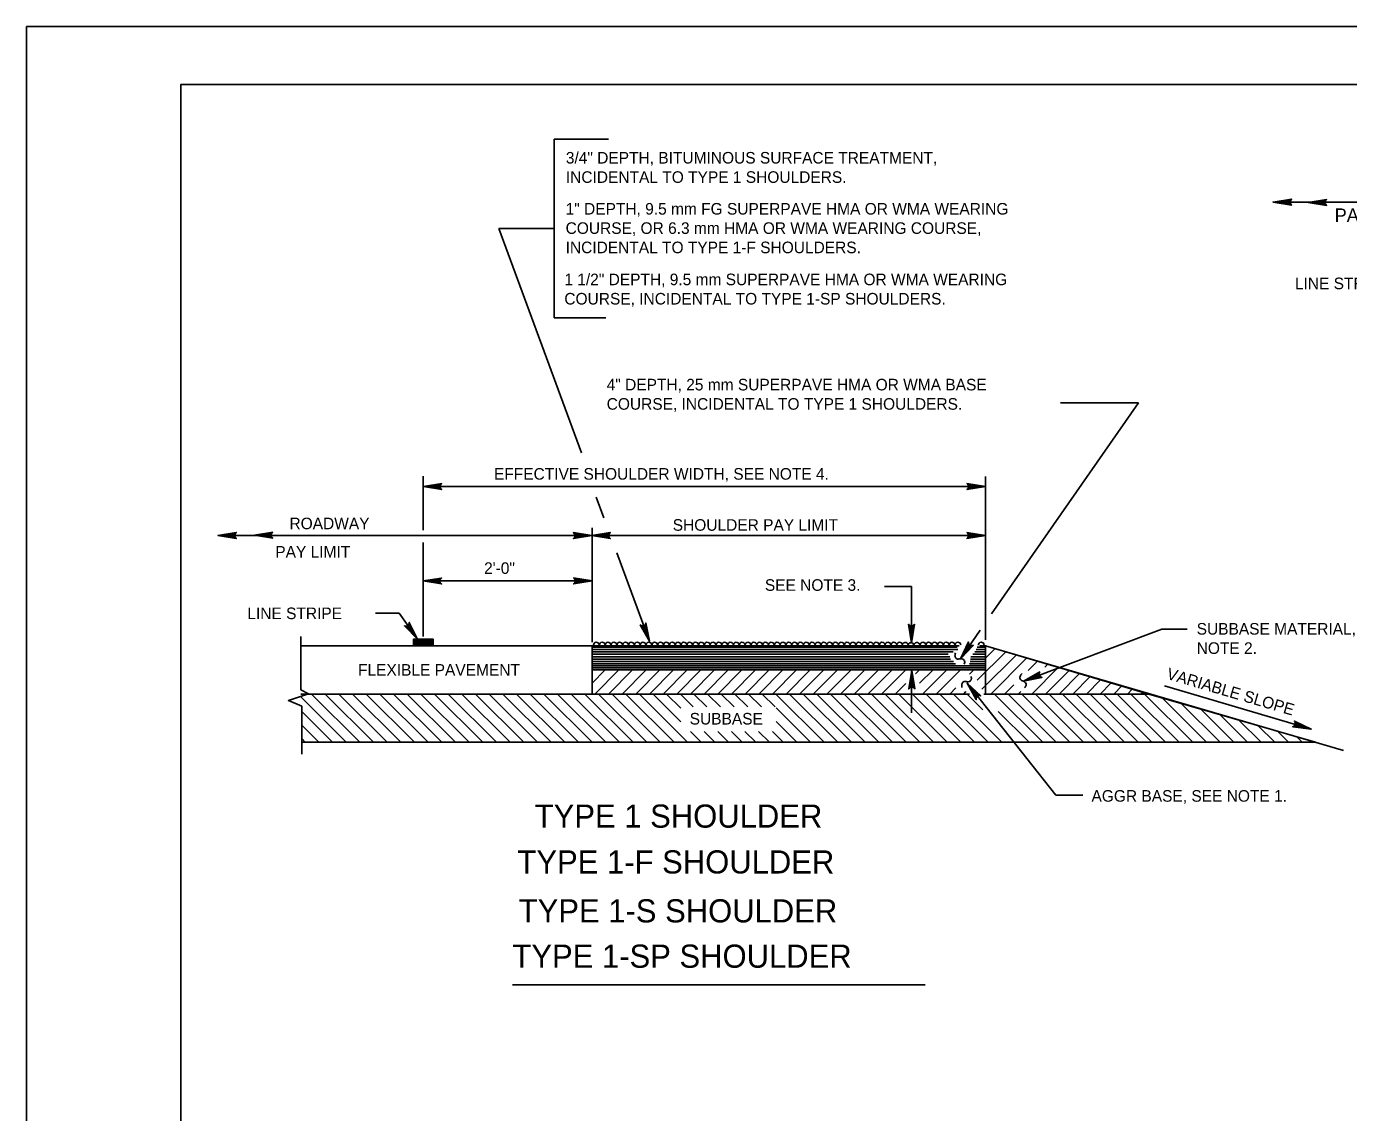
# Model space of a CAD drawing. Extents: x 638216 to 639962, y 297510 to 299292.
# Drawn here: x 638215.9 to 638558.2, y 299010.9 to 299292.2 of the extents above; entities that cross this region are included whole.
import ezdxf

# ---------------------------------------------------------------- set-up
doc = ezdxf.new("R2010")
doc.units = 0
for name, color, linetype in [('1', 7, 'Continuous'), ('2', 7, 'Continuous'), ('3', 7, 'Continuous'), ('PLT-BNDY', 7, 'Continuous')]:
    doc.layers.add(name, color=color, linetype=linetype)

msp = doc.modelspace()

# ---------------------------------------------------------------- linework, layer by layer
at = {"layer": '1'}
msp.add_lwpolyline([(639041.88, 298713.24), (639041.88, 299277.24), (638255.88, 299277.24), (638255.88, 298713.24), (639041.88, 298713.24), (639041.88, 298739.6), (638841.88, 298739.6), (638841.88, 298804.28), (639041.88, 298804.28), (639041.88, 298833.24), (638841.88, 298833.24), (638841.88, 298713.24), (638920.69, 298713.24), (638920.69, 298739.6), (638920.69, 298713.24), (638997.69, 298713.24), (638997.69, 298739.6), (638997.69, 298727.28), (639041.88, 298727.28)], dxfattribs=at)
at = {"layer": '2'}
for p, q in [((638352.54, 299216.78), (638352.54, 299263.08)), ((638366.62, 299263.08), (638352.54, 299263.08)), ((638540.27, 299246.73), (638634.27, 299246.73)), ((638352.54, 299239.93), (638338.17, 299239.93)), ((638359.61, 299181.77), (638338.17, 299239.93)), ((638365.93, 299216.78), (638352.54, 299216.78)), ((638503.83, 299194.7), (638465.79, 299140.08)), ((638483.63, 299194.7), (638503.83, 299194.7)), ((638318.61, 299161.77), (638318.61, 299175.77)), ((638464.2, 299133.35), (638464.2, 299175.7)), ((638318.65, 299173.05), (638464.18, 299173.05)), ((638365.39, 299164.96), (638363.42, 299170.3)), ((638266.88, 299160.36), (638362.28, 299160.36)), ((638362.28, 299160.36), (638464.18, 299160.36)), ((638362.38, 299132.79), (638362.38, 299162.4)), ((638318.61, 299134.22), (638318.61, 299158.59)), ((638376.92, 299133.66), (638368.73, 299155.9)), ((638318.59, 299148.61), (638362.34, 299148.61)), ((638438.08, 299147.18), (638445.02, 299147.18)), ((638445.02, 299132.61), (638445.02, 299147.18)), ((638306.27, 299140.28), (638312.42, 299140.28)), ((638312.42, 299140.28), (638317.03, 299133.74)), ((638286.96, 299120.41), (638286.96, 299134.22)), ((638462.82, 299135.82), (638457.7, 299128.45)), ((638509.87, 299136.15), (638474.05, 299122.67)), ((638509.87, 299136.15), (638516.42, 299136.15)), ((638287.15, 299131.82), (638457.41, 299131.82)), ((638362.34, 299119.32), (638362.34, 299131.82)), ((638462.7, 299131.82), (638464.23, 299131.82)), ((638464.23, 299119.32), (638464.23, 299131.82)), ((638464.23, 299131.82), (638556.9, 299104.7)), ((638506.52, 299119.32), (638464.23, 299131.82)), ((638464.23, 299131.82), (638464.23, 299125.57)), ((638362.34, 299125.57), (638464.23, 299125.57)), ((638464.23, 299125.57), (638362.34, 299125.57)), ((638362.34, 299125.57), (638362.34, 299119.32)), ((638445.02, 299114.41), (638445.02, 299125.57)), ((638286.96, 299119.32), (638460.1, 299119.32)), ((638385.32, 299112.12), (638378.12, 299119.32)), ((638385.32, 299115.66), (638381.65, 299119.32)), ((638388.52, 299115.99), (638385.19, 299119.32)), ((638392.05, 299115.99), (638388.72, 299119.32)), ((638395.59, 299115.99), (638392.26, 299119.32)), ((638399.12, 299115.99), (638395.8, 299119.32)), ((638402.66, 299115.99), (638399.33, 299119.32)), ((638406.2, 299115.99), (638402.87, 299119.32)), ((638409.73, 299115.99), (638406.4, 299119.32)), ((638482.42, 299093.14), (638459.91, 299121.63)), ((638463.81, 299119.32), (638506.52, 299119.32)), ((638506.52, 299119.32), (638549.65, 299106.82)), ((638510.57, 299121.41), (638548.55, 299110.24)), ((638418.9, 299106.82), (638409.97, 299115.75)), ((638390.62, 299106.82), (638387.79, 299109.65)), ((638394.15, 299106.82), (638391.33, 299109.65)), ((638397.69, 299106.82), (638394.86, 299109.65)), ((638401.23, 299106.82), (638398.4, 299109.65)), ((638404.76, 299106.82), (638401.93, 299109.65)), ((638408.3, 299106.82), (638405.47, 299109.65)), ((638411.83, 299106.82), (638409.01, 299109.65)), ((638415.37, 299106.82), (638409.97, 299112.22)), ((638287.15, 299106.82), (638549.65, 299106.82)), ((638549.65, 299106.82), (638287.15, 299106.82)), ((638482.42, 299093.14), (638489.37, 299093.14)), ((638341.72, 299044.02), (638448.55, 299044.02))]:
    msp.add_line(p, q, dxfattribs=at)
for points in [[(638543.19, 299246.18), (638543.02, 299246.51), (638538.65, 299246.75), (638543.19, 299246.18), (638543.43, 299245.98), (638538.65, 299246.75), (638543.02, 299246.97), (638543.18, 299247.29), (638538.65, 299246.75), (638543.43, 299247.51), (638543.18, 299247.29)], [(638543.19, 299246.18), (638543.02, 299246.51), (638538.65, 299246.75), (638543.19, 299246.18), (638543.43, 299245.98), (638538.65, 299246.75), (638543.02, 299246.97), (638543.18, 299247.29), (638538.65, 299246.75), (638543.43, 299247.51), (638543.18, 299247.29)], [(638543.23, 299246.16), (638543.06, 299246.49), (638538.69, 299246.73), (638543.23, 299246.16), (638543.46, 299245.96), (638538.69, 299246.73), (638543.06, 299246.95), (638543.22, 299247.27), (638538.69, 299246.73), (638543.46, 299247.49), (638543.22, 299247.27)], [(638552.3, 299246.08), (638552.13, 299246.41), (638547.76, 299246.65), (638552.3, 299246.08), (638552.53, 299245.89), (638547.76, 299246.65), (638552.12, 299246.87), (638552.28, 299247.2), (638547.76, 299246.65), (638552.53, 299247.41), (638552.28, 299247.2)], [(638552.3, 299246.08), (638552.13, 299246.41), (638547.76, 299246.65), (638552.3, 299246.08), (638552.53, 299245.89), (638547.76, 299246.65), (638552.12, 299246.87), (638552.28, 299247.2), (638547.76, 299246.65), (638552.53, 299247.41), (638552.28, 299247.2)], [(638323.19, 299172.48), (638323.02, 299172.81), (638318.65, 299173.05), (638323.19, 299172.48), (638323.42, 299172.28), (638318.65, 299173.05), (638323.02, 299173.27), (638323.18, 299173.59), (638318.65, 299173.05), (638323.42, 299173.81), (638323.18, 299173.59)], [(638459.63, 299173.62), (638459.8, 299173.29), (638464.18, 299173.05), (638459.63, 299173.62), (638459.4, 299173.82), (638464.18, 299173.05), (638459.81, 299172.84), (638459.65, 299172.51), (638464.18, 299173.05), (638459.4, 299172.29), (638459.65, 299172.51)], [(638269.98, 299159.8), (638269.81, 299160.13), (638265.44, 299160.37), (638269.98, 299159.8), (638270.22, 299159.6), (638265.44, 299160.37), (638269.81, 299160.59), (638269.97, 299160.91), (638265.44, 299160.37), (638270.22, 299161.13), (638269.97, 299160.91)], [(638270.02, 299159.79), (638269.85, 299160.12), (638265.48, 299160.36), (638270.02, 299159.79), (638270.25, 299159.59), (638265.48, 299160.36), (638269.85, 299160.57), (638270.01, 299160.9), (638265.48, 299160.36), (638270.25, 299161.12), (638270.01, 299160.9)], [(638279.43, 299159.89), (638279.27, 299160.22), (638274.89, 299160.46), (638279.43, 299159.89), (638279.67, 299159.69), (638274.89, 299160.46), (638279.26, 299160.68), (638279.42, 299161), (638274.89, 299160.46), (638279.67, 299161.22), (638279.42, 299161)], [(638357.74, 299160.93), (638357.91, 299160.6), (638362.28, 299160.36), (638357.74, 299160.93), (638357.51, 299161.13), (638362.28, 299160.36), (638357.92, 299160.14), (638357.76, 299159.82), (638362.28, 299160.36), (638357.51, 299159.6), (638357.76, 299159.82)], [(638366.82, 299159.79), (638366.66, 299160.12), (638362.28, 299160.36), (638366.82, 299159.79), (638367.06, 299159.59), (638362.28, 299160.36), (638366.65, 299160.57), (638366.81, 299160.9), (638362.28, 299160.36), (638367.06, 299161.12), (638366.81, 299160.9)], [(638459.63, 299160.93), (638459.8, 299160.6), (638464.18, 299160.36), (638459.63, 299160.93), (638459.4, 299161.13), (638464.18, 299160.36), (638459.81, 299160.14), (638459.65, 299159.82), (638464.18, 299160.36), (638459.4, 299159.6), (638459.65, 299159.82)], [(638323.13, 299148.04), (638322.96, 299148.37), (638318.59, 299148.61), (638323.13, 299148.04), (638323.37, 299147.84), (638318.59, 299148.61), (638322.96, 299148.83), (638323.12, 299149.15), (638318.59, 299148.61), (638323.37, 299149.37), (638323.12, 299149.15)], [(638357.8, 299149.18), (638357.97, 299148.85), (638362.34, 299148.61), (638357.8, 299149.18), (638357.57, 299149.38), (638362.34, 299148.61), (638357.97, 299148.4), (638357.81, 299148.07), (638362.34, 299148.61), (638357.57, 299147.85), (638357.81, 299148.07)], [(638315, 299137.55), (638314.82, 299137.22), (638317.15, 299133.51), (638315, 299137.55), (638315.02, 299137.85), (638317.15, 299133.51), (638314.45, 299136.95), (638314.1, 299136.9), (638317.15, 299133.51), (638313.77, 299136.97), (638314.1, 299136.9)], [(638375.08, 299137.06), (638375.45, 299137.02), (638377.17, 299132.99), (638375.08, 299137.06), (638374.82, 299137.21), (638377.17, 299132.99), (638375.88, 299137.17), (638376.13, 299137.43), (638377.17, 299132.99), (638376.25, 299137.74), (638376.13, 299137.43)], [(638445.59, 299137.15), (638445.26, 299136.98), (638445.02, 299132.61), (638445.59, 299137.15), (638445.79, 299137.38), (638445.02, 299132.61), (638444.81, 299136.97), (638444.48, 299137.13), (638445.02, 299132.61), (638444.26, 299137.38), (638444.48, 299137.13)], [(638316.07, 299133.33), (638316.24, 299133.51)], [(638316.07, 299132.16), (638317.42, 299133.51)], [(638316.07, 299132.51), (638317.06, 299133.51)], [(638316.07, 299132.86), (638316.71, 299133.51)], [(638316.07, 299133.22), (638316.36, 299133.51)], [(638316.17, 299131.91), (638317.77, 299133.51)], [(638316.52, 299131.91), (638318.12, 299133.51)], [(638316.88, 299131.91), (638318.48, 299133.51)], [(638317.23, 299131.91), (638318.83, 299133.51)], [(638317.58, 299131.91), (638319.18, 299133.51)], [(638317.94, 299131.91), (638319.54, 299133.51)], [(638318.29, 299131.91), (638319.89, 299133.51)], [(638318.64, 299131.91), (638320.25, 299133.51)], [(638319, 299131.91), (638320.6, 299133.51)], [(638319.35, 299131.91), (638320.95, 299133.51)], [(638319.7, 299131.91), (638321.2, 299133.4)], [(638320.06, 299131.91), (638321.2, 299133.05)], [(638320.41, 299131.91), (638321.2, 299132.69)], [(638320.76, 299131.91), (638321.2, 299132.34)], [(638321, 299131.91), (638321.2, 299132.1)], [(638321.12, 299131.91), (638321.2, 299131.98)], [(638362.34, 299131.75), (638362.41, 299131.82)], [(638362.34, 299131.49), (638456.84, 299131.49)], [(638362.34, 299130.87), (638457.08, 299130.87)], [(638362.34, 299130.24), (638455.87, 299130.24)], [(638362.34, 299129.62), (638454.55, 299129.62)], [(638460.76, 299131.85), (638460.39, 299131.9), (638457.7, 299128.45), (638460.76, 299131.85), (638461.05, 299131.93), (638457.7, 299128.45), (638460.01, 299132.16), (638459.84, 299132.48), (638457.7, 299128.45), (638459.8, 299132.8), (638459.84, 299132.48)], [(638460.89, 299129.62), (638464.23, 299129.62)], [(638461.41, 299130.24), (638464.23, 299130.24)], [(638461.79, 299130.87), (638464.23, 299130.87)], [(638462.08, 299131.49), (638464.23, 299131.49)], [(638462.08, 299122.89), (638469.46, 299130.27)], [(638463.28, 299120.55), (638472.19, 299129.47)], [(638464.23, 299128.57), (638466.73, 299131.08)], [(638362.34, 299128.99), (638454.94, 299128.99)], [(638362.34, 299128.37), (638455.17, 299128.37)], [(638362.34, 299127.74), (638455.89, 299127.74)], [(638362.34, 299127.12), (638456.41, 299127.12)], [(638362.34, 299126.58), (638464.23, 299126.58)], [(638362.34, 299126.07), (638464.23, 299126.07)], [(638460.08, 299127.12), (638464.23, 299127.12)], [(638460.22, 299127.74), (638464.23, 299127.74)], [(638460.36, 299128.37), (638464.23, 299128.37)], [(638460.41, 299128.99), (638464.23, 299128.99)], [(638465.58, 299119.32), (638474.92, 299128.66)], [(638475.24, 299125.44), (638477.65, 299127.85)], [(638476.19, 299119.32), (638483.11, 299126.24)], [(638479.58, 299126.25), (638480.38, 299127.05)], [(638362.34, 299122.14), (638365.76, 299125.57)], [(638363.05, 299119.32), (638369.3, 299125.57)], [(638366.58, 299119.32), (638372.83, 299125.57)], [(638370.12, 299119.32), (638376.37, 299125.57)], [(638373.66, 299119.32), (638379.91, 299125.57)], [(638377.19, 299119.32), (638383.44, 299125.57)], [(638380.73, 299119.32), (638386.98, 299125.57)], [(638384.26, 299119.32), (638390.51, 299125.57)], [(638387.8, 299119.32), (638394.05, 299125.57)], [(638391.33, 299119.32), (638397.58, 299125.57)], [(638394.87, 299119.32), (638401.12, 299125.57)], [(638398.41, 299119.32), (638404.66, 299125.57)], [(638401.94, 299119.32), (638408.19, 299125.57)], [(638405.48, 299119.32), (638411.73, 299125.57)], [(638409.01, 299119.32), (638415.26, 299125.57)], [(638412.55, 299119.32), (638418.8, 299125.57)], [(638416.08, 299119.32), (638422.33, 299125.57)], [(638419.62, 299119.32), (638425.87, 299125.57)], [(638423.15, 299119.32), (638429.4, 299125.57)], [(638426.69, 299119.32), (638432.94, 299125.57)], [(638430.22, 299119.32), (638436.47, 299125.57)], [(638433.76, 299119.32), (638440.01, 299125.57)], [(638437.3, 299119.32), (638443.55, 299125.57)], [(638444.55, 299120.9), (638444.87, 299121.07), (638445.11, 299125.44), (638444.55, 299120.9), (638444.35, 299120.66), (638445.11, 299125.44), (638445.33, 299121.07), (638445.66, 299120.91), (638445.11, 299125.44), (638445.87, 299120.66), (638445.66, 299120.91)], [(638446.05, 299124.54), (638447.08, 299125.57)], [(638447.15, 299122.1), (638450.62, 299125.57)], [(638447.9, 299119.32), (638454.15, 299125.57)], [(638451.44, 299119.32), (638457.69, 299125.57)], [(638460.07, 299124.42), (638461.22, 299125.57)], [(638478.5, 299123.73), (638478.23, 299123.98), (638474.05, 299122.67), (638478.5, 299123.73), (638478.79, 299123.63), (638474.05, 299122.67), (638478.06, 299124.41), (638478.1, 299124.77), (638474.05, 299122.67), (638478.25, 299125.06), (638478.1, 299124.77)], [(638479.72, 299119.32), (638485.84, 299125.43)], [(638483.26, 299119.32), (638488.56, 299124.63)], [(638486.79, 299119.32), (638491.3, 299123.82)], [(638490.33, 299119.32), (638494.02, 299123.01)], [(638287.15, 299116.16), (638283.73, 299117.65), (638288.92, 299119.38), (638286.96, 299120.41)], [(638302.23, 299106.82), (638289.73, 299119.32)], [(638305.77, 299106.82), (638293.27, 299119.32)], [(638309.3, 299106.82), (638296.8, 299119.32)], [(638312.84, 299106.82), (638300.34, 299119.32)], [(638316.37, 299106.82), (638303.87, 299119.32)], [(638319.91, 299106.82), (638307.41, 299119.32)], [(638323.44, 299106.82), (638310.94, 299119.32)], [(638326.98, 299106.82), (638314.48, 299119.32)], [(638330.51, 299106.82), (638318.01, 299119.32)], [(638334.05, 299106.82), (638321.55, 299119.32)], [(638337.58, 299106.82), (638325.08, 299119.32)], [(638341.12, 299106.82), (638328.62, 299119.32)], [(638344.66, 299106.82), (638332.16, 299119.32)], [(638348.19, 299106.82), (638335.69, 299119.32)], [(638351.73, 299106.82), (638339.23, 299119.32)], [(638355.26, 299106.82), (638342.76, 299119.32)], [(638358.8, 299106.82), (638346.3, 299119.32)], [(638362.33, 299106.82), (638349.83, 299119.32)], [(638365.87, 299106.82), (638353.37, 299119.32)], [(638369.41, 299106.82), (638356.91, 299119.32)], [(638372.94, 299106.82), (638360.44, 299119.32)], [(638376.48, 299106.82), (638363.98, 299119.32)], [(638380.01, 299106.82), (638367.51, 299119.32)], [(638383.55, 299106.82), (638371.05, 299119.32)], [(638387.08, 299106.82), (638374.58, 299119.32)], [(638422.44, 299106.82), (638409.94, 299119.32)], [(638425.97, 299106.82), (638413.47, 299119.32)], [(638429.51, 299106.82), (638417.01, 299119.32)], [(638433.05, 299106.82), (638420.55, 299119.32)], [(638436.58, 299106.82), (638424.08, 299119.32)], [(638440.12, 299106.82), (638427.62, 299119.32)], [(638443.65, 299106.82), (638431.15, 299119.32)], [(638447.19, 299106.82), (638434.69, 299119.32)], [(638450.72, 299106.82), (638438.22, 299119.32)], [(638440.83, 299119.32), (638443.57, 299122.06)], [(638454.26, 299106.82), (638441.76, 299119.32)], [(638457.79, 299106.82), (638445.29, 299119.32)], [(638461.33, 299106.82), (638448.83, 299119.32)], [(638464.86, 299106.82), (638452.36, 299119.32)], [(638454.97, 299119.32), (638456.55, 299120.89)], [(638468.4, 299106.82), (638455.9, 299119.32)], [(638458.51, 299119.32), (638459.13, 299119.94)], [(638462.69, 299118.9), (638462.33, 299118.83), (638459.43, 299122.11), (638462.69, 299118.9), (638462.99, 299118.84), (638459.43, 299122.11), (638461.97, 299118.55), (638461.81, 299118.22), (638459.43, 299122.11), (638461.8, 299117.89), (638461.81, 299118.22)], [(638463.51, 299115.24), (638459.43, 299119.32)], [(638479.01, 299106.82), (638466.51, 299119.32)], [(638469.12, 299119.32), (638471.52, 299121.73)], [(638482.54, 299106.82), (638470.04, 299119.32)], [(638472.65, 299119.32), (638473.34, 299120.01)], [(638486.08, 299106.82), (638473.58, 299119.32)], [(638489.61, 299106.82), (638477.11, 299119.32)], [(638493.15, 299106.82), (638480.65, 299119.32)], [(638496.68, 299106.82), (638484.18, 299119.32)], [(638500.22, 299106.82), (638487.72, 299119.32)], [(638503.76, 299106.82), (638491.26, 299119.32)], [(638493.86, 299119.32), (638496.75, 299122.21)], [(638507.29, 299106.82), (638494.79, 299119.32)], [(638497.4, 299119.32), (638499.48, 299121.4)], [(638510.83, 299106.82), (638498.33, 299119.32)], [(638500.93, 299119.32), (638502.21, 299120.59)], [(638514.36, 299106.82), (638501.86, 299119.32)], [(638504.47, 299119.32), (638504.94, 299119.79)], [(638517.9, 299106.82), (638505.4, 299119.32)], [(638298.7, 299106.82), (638286.83, 299118.68)], [(638287.15, 299103.7), (638287.15, 299116.16)], [(638521.43, 299106.82), (638509.92, 299118.34)], [(638524.97, 299106.82), (638514.9, 299116.89)], [(638295.16, 299106.82), (638287.15, 299114.83)], [(638475.47, 299106.82), (638467.49, 299114.8)], [(638528.5, 299106.82), (638519.87, 299115.45)], [(638532.04, 299106.82), (638524.85, 299114.01)], [(638535.58, 299106.82), (638529.83, 299112.56)], [(638544.35, 299112.07), (638544.42, 299111.7), (638548.55, 299110.24), (638544.35, 299112.07), (638544.19, 299112.33), (638548.55, 299110.24), (638544.3, 299111.26), (638544.05, 299111), (638548.55, 299110.24), (638543.76, 299110.86), (638544.05, 299111)], [(638291.62, 299106.82), (638287.15, 299111.29)], [(638539.11, 299106.82), (638534.81, 299111.12)], [(638542.65, 299106.82), (638539.79, 299109.68)], [(638288.09, 299106.82), (638287.15, 299107.76)], [(638546.18, 299106.82), (638544.77, 299108.24)]]:
    msp.add_lwpolyline(points, dxfattribs=at)
msp.add_lwpolyline([(638316.07, 299131.91), (638316.07, 299133.51), (638321.2, 299133.51), (638321.2, 299131.91)], close=True, dxfattribs=at)
for centre in [(638363.47, 299131.95), (638364.98, 299131.95), (638366.49, 299131.95), (638368, 299131.95), (638369.51, 299131.95), (638371.02, 299131.95), (638372.53, 299131.95), (638374.04, 299131.95), (638375.55, 299131.95), (638377.06, 299131.95), (638378.57, 299131.95), (638380.08, 299131.95), (638381.59, 299131.95), (638383.1, 299131.95), (638384.6, 299131.95), (638386.11, 299131.95), (638387.62, 299131.95), (638389.13, 299131.95), (638390.64, 299131.95), (638392.15, 299131.95), (638393.66, 299131.95), (638395.17, 299131.95), (638396.68, 299131.95), (638398.19, 299131.95), (638399.7, 299131.95), (638401.21, 299131.95), (638402.72, 299131.95), (638404.23, 299131.95), (638405.74, 299131.95), (638407.25, 299131.95), (638408.76, 299131.95), (638410.27, 299131.95), (638411.78, 299131.95), (638413.29, 299131.95), (638414.8, 299131.95), (638416.31, 299131.95), (638417.82, 299131.95), (638419.33, 299131.95), (638420.84, 299131.95), (638422.35, 299131.95), (638423.86, 299131.95), (638425.37, 299131.95), (638426.88, 299131.95), (638428.39, 299131.95), (638429.9, 299131.95), (638431.41, 299131.95), (638432.92, 299131.95), (638434.43, 299131.95), (638435.94, 299131.95), (638437.45, 299131.95), (638438.96, 299131.95), (638440.47, 299131.95), (638441.98, 299131.95), (638443.42, 299131.9), (638444.9, 299131.86), (638446.43, 299131.9), (638448.01, 299131.95), (638449.52, 299131.95), (638451.03, 299131.95), (638452.54, 299131.95), (638454.05, 299131.95), (638455.56, 299131.95), (638457.07, 299131.95), (638463.11, 299131.95)]:
    msp.add_arc(centre, 0.762, 10.6519, 178.7199, dxfattribs=at)
for points in [[(638456.41, 299129.97), (638456.31, 299129.51), (638456.5, 299128.68), (638457.15, 299128.36), (638457.7, 299128.45), (638458.33, 299128.35), (638458.8, 299127.82), (638458.84, 299127.53), (638458.72, 299127.08)], [(638458.14, 299120.97), (638458.05, 299121.43), (638458.23, 299122.26), (638458.89, 299122.58), (638459.43, 299122.49), (638460.06, 299122.59), (638460.53, 299123.13), (638460.57, 299123.41), (638460.46, 299123.86)], [(638473.7, 299124.63), (638473.38, 299124.27), (638473.13, 299123.46), (638473.54, 299122.86), (638474.05, 299122.67), (638474.55, 299122.26), (638474.69, 299121.56), (638474.58, 299121.3), (638474.26, 299120.96)]]:
    msp.add_spline(points, degree=3, dxfattribs=at)
at = {"layer": 'PLT-BNDY'}
msp.add_lwpolyline([(638215.88, 299292.24), (639056.88, 299292.24), (639056.88, 298698.24), (638215.88, 298698.24)], close=True, dxfattribs=at)

# ---------------------------------------------------------------- texts
at = {"layer": '3'}
for s, height, p in [('3/4" DEPTH, BITUMINOUS SURFACE TREATMENT,', 3, (638355.55, 299256.72)), ('INCIDENTAL TO TYPE 1 SHOULDERS.', 3, (638355.55, 299251.72)), ('1" DEPTH, 9.5 mm FG SUPERPAVE HMA OR WMA WEARING', 3, (638355.49, 299243.5)), ('PAY LIMIT', 3.5, (638554.61, 299241.59)), ('COURSE, OR 6.3 mm HMA OR WMA WEARING COURSE,', 3, (638355.49, 299238.5)), ('INCIDENTAL TO TYPE 1-F SHOULDERS.', 3, (638355.49, 299233.5)), ('1 1/2" DEPTH, 9.5 mm SUPERPAVE HMA OR WMA WEARING', 3, (638355.16, 299225.21)), ('LINE STRIPE', 3, (638544.32, 299224.18)), ('COURSE, INCIDENTAL TO TYPE 1-SP SHOULDERS.', 3, (638355.16, 299220.21)), ('4" DEPTH, 25 mm SUPERPAVE HMA OR WMA BASE', 3, (638366.12, 299197.96)), ('COURSE, INCIDENTAL TO TYPE 1 SHOULDERS.', 3, (638366.12, 299192.96)), ('EFFECTIVE SHOULDER WIDTH, SEE NOTE 4.', 3, (638336.94, 299174.84)), ('ROADWAY', 3, (638283.99, 299162)), ('SHOULDER PAY LIMIT', 3, (638383.22, 299161.61)), ('PAY LIMIT', 3, (638280.32, 299154.65)), ('2\'-0"', 3, (638334.37, 299150.43)), ('SEE NOTE 3.', 3, (638407.08, 299146.05)), ('LINE STRIPE', 3, (638273.08, 299138.72)), ('SUBBASE MATERIAL, SEE', 3, (638518.88, 299134.71)), ('NOTE 2.', 3, (638518.88, 299129.71)), ('FLEXIBLE PAVEMENT', 3, (638301.74, 299124.07)), ('SUBBASE', 3, (638387.61, 299111.42)), ('AGGR BASE, SEE NOTE 1.', 3, (638491.65, 299091.43)), ('TYPE 1 SHOULDER', 6, (638347.49, 299084.7)), ('TYPE 1-F SHOULDER', 6, (638343.02, 299072.83)), ('TYPE 1-S SHOULDER', 6, (638343.34, 299060.16)), ('TYPE 1-SP SHOULDER', 6, (638341.72, 299048.42))]:
    msp.add_text(s, height=height, dxfattribs=at).set_placement(p)
msp.add_text('VARIABLE SLOPE', height=3, rotation=343.6873, dxfattribs=at).set_placement((638510.89, 299123.29))

doc.saveas('drawing.dxf')
